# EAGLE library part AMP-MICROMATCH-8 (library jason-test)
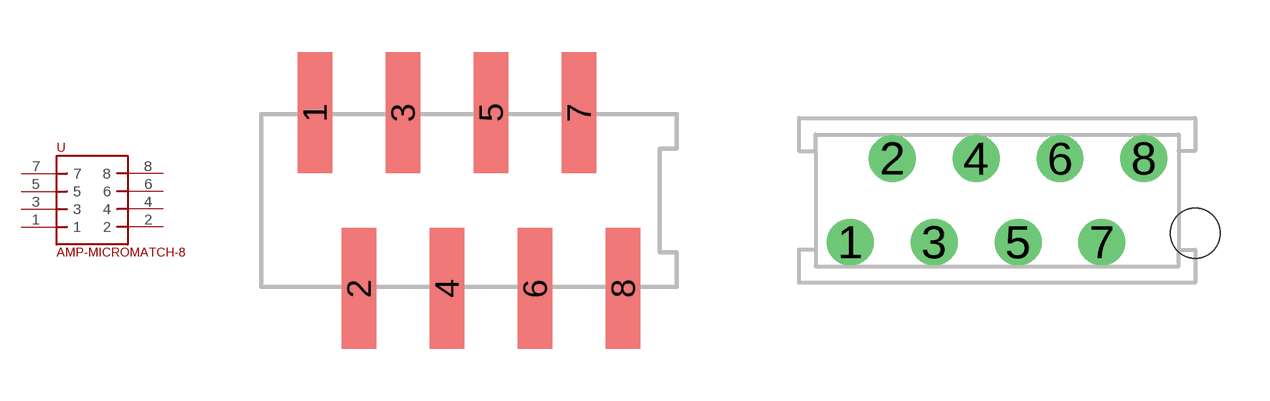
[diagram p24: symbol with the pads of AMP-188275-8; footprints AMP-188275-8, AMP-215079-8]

Designator prefix -

## AMP-MICROMATCH-8188275-SMT  [AMP-188275-8]
1  1
2  2
3  3
4  4
5  5
6  6
7  7
8  8

## AMP-MICROMATCH-8215079-TH  [AMP-215079-8]
Pads as for AMP-188275-8

## AMP-MICROMATCH-8215464-MALE  [AMP-215464-8]
Pads as for AMP-188275-8

## Footprint AMP-188275-8 (pad centres in mm)
smd 1 x 3.5: 1 -4.445,2.54; 2 -3.175,-2.54; 3 -1.905,2.54; 4 -0.635,-2.54; 5 0.635,2.54; 6 1.905,-2.54; 7 3.175,2.54; 8 4.445,-2.54

## Footprint AMP-215079-8 (pad centres in mm)
drill 0.8 pad 1.422 round: 1 -4.445,-1.27; 2 -3.175,1.27; 3 -1.905,-1.27; 4 -0.635,1.27; 5 0.635,-1.27; 6 1.905,1.27; 7 3.175,-1.27; 8 4.445,1.27
hole 1.5 at 6,-1

## Footprint AMP-215464-8 (pad centres in mm)
drill 0.8 round: 1 -4.445,-1.27; 2 -3.175,1.27; 3 -1.905,-1.27; 4 -0.635,1.27; 5 0.635,-1.27; 6 1.905,1.27; 7 3.175,-1.27; 8 4.445,1.27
